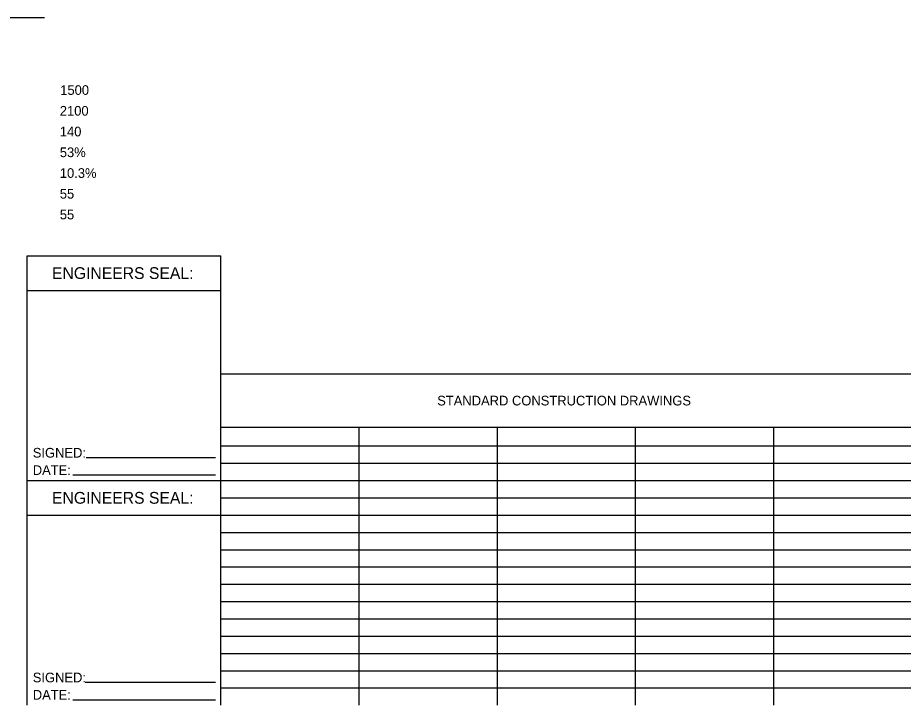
# Model space of a CAD drawing. Extents: x 0 to 72, y -85 to 22.
# Drawn here: x 48.81 to 61.62, y -12.31 to -2.37 of the extents above; entities that cross this region are included whole.
import ezdxf

# ---------------------------------------------------------------- set-up
doc = ezdxf.new("R2010")
doc.units = 0
doc.layers.add('GM_X_Township', color=7, linetype='Continuous')

msp = doc.modelspace()

# ---------------------------------------------------------------- linework, layer by layer
at = {"layer": 'GM_X_Township'}
for p, q in [((49.196, -2.366), (47.946, -2.366)), ((48.946, -9.059), (48.946, -5.809)), ((48.946, -5.809), (51.746, -5.809)), ((51.746, -12.309), (51.746, -5.809)), ((48.946, -6.309), (51.746, -6.309)), ((51.746, -7.517), (65.196, -7.517)), ((51.746, -8.288), (65.196, -8.288)), ((53.746, -12.309), (53.746, -8.288)), ((55.746, -12.309), (55.746, -8.288)), ((57.746, -12.309), (57.746, -8.288)), ((59.746, -12.309), (59.746, -8.288)), ((51.746, -8.559), (65.196, -8.559)), ((49.8, -8.727), (51.668, -8.727)), ((51.746, -8.809), (65.196, -8.809)), ((48.946, -12.309), (48.946, -9.059)), ((48.946, -9.059), (51.746, -9.059)), ((49.604, -8.978), (51.668, -8.978)), ((51.746, -9.059), (65.196, -9.059)), ((51.746, -9.309), (65.196, -9.309)), ((48.946, -9.559), (51.746, -9.559)), ((51.746, -9.559), (65.196, -9.559)), ((51.746, -9.809), (65.196, -9.809)), ((51.746, -10.059), (65.196, -10.059)), ((51.746, -10.309), (65.196, -10.309)), ((51.746, -10.559), (65.196, -10.559)), ((51.746, -10.809), (65.196, -10.809)), ((51.746, -11.059), (65.196, -11.059)), ((51.746, -11.309), (65.196, -11.309)), ((51.746, -11.559), (65.196, -11.559)), ((51.746, -11.809), (65.196, -11.809)), ((49.783, -11.977), (51.668, -11.977)), ((51.746, -12.059), (65.196, -12.059)), ((49.604, -12.228), (51.668, -12.228))]:
    msp.add_line(p, q, dxfattribs=at)

# ---------------------------------------------------------------- texts
for s, height, p in [('1500', 0.14, (49.423, -3.482)), ('2100', 0.14, (49.417, -3.782)), ('140', 0.14, (49.417, -4.082)), ('53%', 0.14, (49.417, -4.382)), ('10.3%', 0.14, (49.417, -4.682)), ('55', 0.14, (49.417, -4.982)), ('55', 0.14, (49.417, -5.282)), ('ENGINEERS SEAL:', 0.17, (49.304, -6.144)), ('STANDARD CONSTRUCTION DRAWINGS', 0.14, (54.876, -7.973)), ('SIGNED:', 0.14, (49.026, -8.727)), ('DATE:', 0.14, (49.026, -8.978)), ('ENGINEERS SEAL:', 0.17, (49.304, -9.394)), ('SIGNED:', 0.14, (49.026, -11.977)), ('DATE:', 0.14, (49.026, -12.228))]:
    msp.add_text(s, height=height, dxfattribs=at).set_placement(p)

doc.saveas('drawing.dxf')
